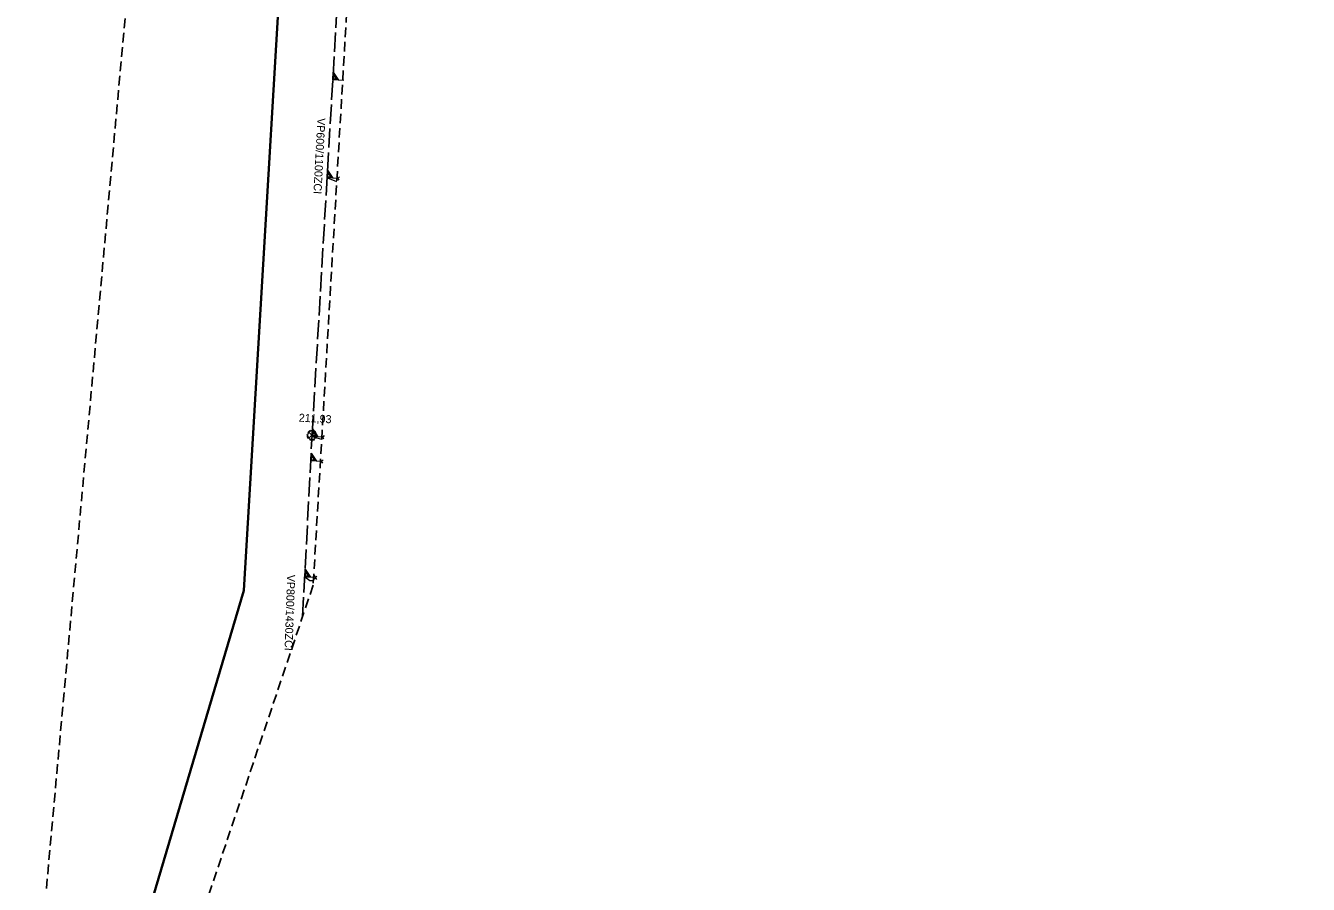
# Model space of a CAD drawing. Extents: x -744446 to -743929, y -1041261 to -1040599.
# Drawn here: x -744445.1 to -744316.9, y -1041175.1 to -1041089.2 of the extents above; entities that cross this region are included whole.
import ezdxf

# ---------------------------------------------------------------- set-up
doc = ezdxf.new("R2010")
doc.units = 0
doc.header["$LTSCALE"] = 0.32
doc.linetypes.add('LONG_DASHED', pattern=[7.5, 6, -1.5])
doc.linetypes.add('MEDIUM_DASHED', pattern=[4.5, 3, -1.5])
for name, color, linetype, lineweight in [('1', 7, 'MEDIUM_DASHED', 25), ('18', 7, 'Continuous', 13), ('20', 7, 'LONG_DASHED', 13), ('49', 7, 'MEDIUM_DASHED', 13)]:
    doc.layers.add(name, color=color, linetype=linetype, lineweight=lineweight)

msp = doc.modelspace()

# ---------------------------------------------------------------- linework, layer by layer
at = {"layer": '1'}
msp.add_lwpolyline([(-744438.077, -1041259.731), (-744438.679, -1041250.888), (-744445.125, -1041198.426), (-744434.434, -1041080.103), (-744426.87, -1040938.41), (-744425.446, -1040859.072), (-744414.192, -1040822.094), (-744390.076, -1040771.45), (-744357.118, -1040726.434), (-744307.278, -1040693.475), (-744241.36, -1040670.967), (-743937.498, -1040598.618), (-743928.655, -1040619.519), (-744129.684, -1040665.585), (-744218.109, -1040687.29), (-744311.358, -1040718.641), (-744361.198, -1040777.323), (-744391.745, -1040864.141), (-744411.355, -1041059.185), (-744416.379, -1041145.154), (-744432.569, -1041193.163), (-744432.047, -1041202.053), (-744422.803, -1041230.992), (-744424.813, -1041260.936)], close=True, dxfattribs=at)
at = {"layer": '18'}
for p, q in [((-744413.757, -1041104.325), (-744414.046, -1041104.644)), ((-744413.789, -1041104.662), (-744414.011, -1041104.277)), ((-744416.185, -1041130.454), (-744416.803, -1041129.836)), ((-744416.803, -1041130.454), (-744416.186, -1041129.837)), ((-744415.27, -1041130.193), (-744415.556, -1041130.514)), ((-744415.3, -1041130.53), (-744415.524, -1041130.147)), ((-744415.396, -1041132.62), (-744415.682, -1041132.941)), ((-744415.426, -1041132.957), (-744415.65, -1041132.574)), ((-744415.998, -1041144.234), (-744416.284, -1041144.555)), ((-744416.028, -1041144.571), (-744416.252, -1041144.188))]:
    msp.add_line(p, q, dxfattribs=at)
for points in [[(-744413.321, -1041094.678), (-744414.415, -1041094.614), (-744414.37, -1041093.846), (-744413.838, -1041094.648)], [(-744413.953, -1041094.591), (-744414.368, -1041094.567), (-744414.335, -1041094.002), (-744413.952, -1041094.591)], [(-744414.034, -1041094.54), (-744414.324, -1041094.523), (-744414.303, -1041094.151), (-744414.034, -1041094.541)], [(-744413.896, -1041104.477), (-744414.989, -1041104.413), (-744414.944, -1041103.645), (-744414.412, -1041104.447)], [(-744414.528, -1041104.39), (-744414.942, -1041104.366), (-744414.909, -1041103.801), (-744414.526, -1041104.39)], [(-744414.608, -1041104.339), (-744414.899, -1041104.321), (-744414.877, -1041103.95), (-744414.608, -1041104.34)], [(-744416.991, -1041130.075), (-744416.997, -1041130.152), (-744416.992, -1041130.229), (-744416.975, -1041130.304), (-744416.946, -1041130.375), (-744416.906, -1041130.441), (-744416.89, -1041130.463)], [(-744416.646, -1041129.683), (-744416.717, -1041129.711), (-744416.784, -1041129.75), (-744416.844, -1041129.798), (-744416.895, -1041129.855), (-744416.919, -1041129.889)], [(-744415.407, -1041130.346), (-744416.501, -1041130.289), (-744416.461, -1041129.52), (-744415.924, -1041130.319)], [(-744416.04, -1041130.263), (-744416.454, -1041130.242), (-744416.425, -1041129.677), (-744416.038, -1041130.263)], [(-744416.12, -1041130.212), (-744416.412, -1041130.197), (-744416.393, -1041129.825), (-744416.12, -1041130.213)], [(-744416.105, -1041129.866), (-744416.155, -1041129.808), (-744416.213, -1041129.758), (-744416.278, -1041129.717), (-744416.349, -1041129.688), (-744416.398, -1041129.674)], [(-744416.11, -1041130.452), (-744416.069, -1041130.387), (-744416.038, -1041130.317), (-744416.019, -1041130.242), (-744416.011, -1041130.166), (-744416.016, -1041130.089), (-744416.022, -1041130.054)], [(-744416.733, -1041130.592), (-744416.663, -1041130.623), (-744416.588, -1041130.642), (-744416.512, -1041130.649), (-744416.435, -1041130.644), (-744416.36, -1041130.627), (-744416.288, -1041130.599), (-744416.228, -1041130.564)], [(-744415.533, -1041132.773), (-744416.627, -1041132.716), (-744416.587, -1041131.947), (-744416.05, -1041132.746)], [(-744416.166, -1041132.69), (-744416.58, -1041132.669), (-744416.551, -1041132.104), (-744416.164, -1041132.69)], [(-744416.246, -1041132.639), (-744416.538, -1041132.624), (-744416.519, -1041132.252), (-744416.246, -1041132.64)], [(-744416.135, -1041144.387), (-744417.229, -1041144.33), (-744417.189, -1041143.561), (-744416.652, -1041144.36)], [(-744416.768, -1041144.304), (-744417.182, -1041144.283), (-744417.153, -1041143.718), (-744416.766, -1041144.304)], [(-744416.848, -1041144.253), (-744417.14, -1041144.238), (-744417.121, -1041143.866), (-744416.848, -1041144.254)]]:
    msp.add_lwpolyline(points, dxfattribs=at)
msp.add_lwpolyline([(-744416.058, -1041130.146), (-744416.06, -1041130.1), (-744416.067, -1041130.055), (-744416.079, -1041130.011), (-744416.095, -1041129.968), (-744416.116, -1041129.927), (-744416.141, -1041129.889), (-744416.17, -1041129.853), (-744416.202, -1041129.821), (-744416.238, -1041129.792), (-744416.276, -1041129.767), (-744416.317, -1041129.747), (-744416.36, -1041129.73), (-744416.404, -1041129.718), (-744416.449, -1041129.711), (-744416.495, -1041129.709), (-744416.541, -1041129.711), (-744416.586, -1041129.718), (-744416.63, -1041129.73), (-744416.673, -1041129.747), (-744416.714, -1041129.767), (-744416.752, -1041129.792), (-744416.788, -1041129.821), (-744416.82, -1041129.853), (-744416.849, -1041129.889), (-744416.874, -1041129.928), (-744416.895, -1041129.968), (-744416.911, -1041130.011), (-744416.923, -1041130.055), (-744416.93, -1041130.1), (-744416.933, -1041130.146), (-744416.93, -1041130.192), (-744416.923, -1041130.237), (-744416.911, -1041130.281), (-744416.895, -1041130.324), (-744416.874, -1041130.365), (-744416.849, -1041130.403), (-744416.82, -1041130.439), (-744416.788, -1041130.471), (-744416.752, -1041130.5), (-744416.714, -1041130.525), (-744416.673, -1041130.546), (-744416.63, -1041130.562), (-744416.586, -1041130.574), (-744416.541, -1041130.581), (-744416.495, -1041130.584), (-744416.449, -1041130.581), (-744416.404, -1041130.574), (-744416.36, -1041130.562), (-744416.317, -1041130.546), (-744416.276, -1041130.525), (-744416.238, -1041130.5), (-744416.202, -1041130.471), (-744416.17, -1041130.439), (-744416.141, -1041130.403), (-744416.116, -1041130.365), (-744416.095, -1041130.324), (-744416.079, -1041130.281), (-744416.067, -1041130.237), (-744416.06, -1041130.192)], close=True, dxfattribs=at)
at = {"layer": '20', "linetype": 'Continuous', "lineweight": 35}
msp.add_lwpolyline([(-744429.62, -1041252.21), (-744428.789, -1041237.94), (-744437.959, -1041195.193), (-744423.3, -1041145.69), (-744417.879, -1041053.98), (-744409.949, -1040917.67), (-744407.76, -1040880.01), (-744407.219, -1040869.23), (-744404.395, -1040847.829), (-744400.25, -1040827.35), (-744393.491, -1040807.621), (-744384.879, -1040787.9), (-744372.238, -1040768.547), (-744361.26, -1040752.62), (-744345.317, -1040736.555), (-744330.739, -1040723.14), (-744312.333, -1040710.859), (-744294.67, -1040700.75), (-744274.728, -1040692.583), (-744254.699, -1040686.49), (-744133.87, -1040657.39), (-743953.289, -1040613.85), (-743946.017, -1040612.141)], dxfattribs=at)
at = {"layer": '20', "lineweight": 25}
msp.add_lwpolyline([(-744417.433, -1041148.278), (-744416.493, -1041130.146), (-744413.585, -1041080.42)], dxfattribs=at)
at = {"layer": '49'}
for p, q in [((-744414.022, -1041104.817), (-744414.988, -1041104.419)), ((-744415.527, -1041130.572), (-744416.5, -1041130.295))]:
    msp.add_line(p, q, dxfattribs=at)
msp.add_lwpolyline([(-744416.354, -1041144.724), (-744416.714, -1041144.703), (-744417.228, -1041144.336)], dxfattribs=at)

# ---------------------------------------------------------------- texts
at = {"layer": '1'}
for s, rotation, p in [('VP600/1100ZCI ', 267, (-744415.954, -1041098.417)), ('211,93', 357, (-744417.834, -1041128.789)), ('VP800/1430ZCI ', 268, (-744418.977, -1041144.088))]:
    msp.add_text(s, height=0.8, rotation=rotation, dxfattribs=at).set_placement(p)

doc.saveas('drawing.dxf')
